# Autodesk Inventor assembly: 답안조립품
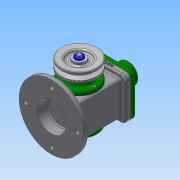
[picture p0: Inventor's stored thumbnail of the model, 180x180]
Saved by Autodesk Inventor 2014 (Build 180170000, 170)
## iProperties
Created: 2018-10
Part Number: 답안조립품
Document SubType Name: Assembly
Designer: Administrator
Author: Administrator
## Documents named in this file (18)
- C:\Users\Administrator\Desktop\481007V1040\답안조립품.iam
- C:\Users\Administrator\Desktop\481007V1040\E-링.ipt
- C:\Users\Administrator\Desktop\481007V1040\V-벨트풀리.ipt
- C:\Users\Administrator\Desktop\481007V1040\덮개.ipt
- C:\Users\Administrator\Desktop\481007V1040\뒤커버.ipt
- C:\Users\Administrator\Desktop\481007V1040\링크.ipt
- C:\Users\Administrator\Desktop\481007V1040\베어링 17 x 40 x 12.ipt
- C:\Users\Administrator\Desktop\481007V1040\본체.ipt
- C:\Users\Administrator\Desktop\481007V1040\볼트 M4 x 8.ipt
- C:\Users\Administrator\Desktop\481007V1040\볼트 M4 x 10.ipt
- C:\Users\Administrator\Desktop\481007V1040\슬라이더.ipt
- C:\Users\Administrator\Desktop\481007V1040\앞커버.ipt
- C:\Users\Administrator\Desktop\481007V1040\오일 실 17 30 8.ipt
- C:\Users\Administrator\Desktop\481007V1040\와셔 4x16.ipt
- C:\Users\Administrator\Desktop\481007V1040\클레비스 핀 6 x 22.ipt
- 클레비스 핀 6 x 22.ipt
- C:\Users\Administrator\Desktop\481007V1040\키 4 x 4 x 12.ipt
- C:\Users\Administrator\Desktop\481007V1040\편심축.ipt
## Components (2 placed, 2 different names)
1. V-벨트풀리:1
2. E-링:1
